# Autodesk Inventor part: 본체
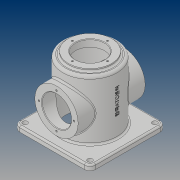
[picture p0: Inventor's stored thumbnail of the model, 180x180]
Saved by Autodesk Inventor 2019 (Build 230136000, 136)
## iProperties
Created: 2019-03
Part Number: 본체
Material: 일반
Document SubType Name: Modeling
Designer: PC312-08
Density: 1 g/cm^3
Appearance: 기본값
Mass: 414.937 g
Surface Area: 1160.06 cm^2
Volume: 414.937 cm^3
Author: PC312-08
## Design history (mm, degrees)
sketch "스케치1"
  geometry: C1 r 50 at (0, 0); 1 further point
  constraints: 1 centre point, 1 coincident
  dimensions: "d0" = 100 diameter of C1
extrude "돌출1" new body sketch "스케치1" stored distance "d1" = 110; taper "d2" = 0 deg
sketch "스케치2"
  geometry: L1 (-70, -70)-(70, -70); L2 (70, -70)-(70, 70); L3 (70, 70)-(-70, 70); L4 (-70, 70)-(-70, -70); L5 (-70, -70)-(70, 70); L6 (70, -70)-(-70, 70); 1 further point
  constraints: 12 end point, 2 midpoint, 2 parallel, 1 horizontal, 1 perpendicular
  dimensions: "d3" = 140 distance of L3.end L2.end; "d4" = 140 distance of L2.end L1.end
extrude "돌출2" join sketch "스케치2" distance "d5" = 10; taper "d6" = 0 deg
sketch "스케치3"
  geometry: C1 r 40 at (0, 0); 1 further point
  constraints: 1 centre point, 1 coincident
  dimensions: "d7" = 80 diameter of C1
extrude "돌출3" join sketch "스케치3" distance "d8" = 5; taper "d9" = 0 deg
sketch "스케치4"
  geometry: C1 r 45 at (0, 0); 1 further point
  constraints: 1 centre point, 1 coincident
  dimensions: "d10" = 90 diameter of C1
extrude "돌출4" cut sketch "스케치4" distance "d11" = 112; taper "d12" = 0 deg
sketch "스케치5"
  geometry: C1 r 27 at (0, 0); 1 further point
  constraints: 1 centre point, 1 coincident
  dimensions: "d13" = 54 diameter of C1
extrude "돌출5" cut sketch "스케치5" distance "d14" = 13; taper "d15" = 0 deg
node "작업 평면1"
sketch "스케치6"
  geometry: L1 (70, -65)-(-70, -65) reference; C1 r 40 at (0, -5); 1 further point
  constraints: 1 centre point, 1 vertical alignment
  dimensions: "d17" = 80 diameter of C1; "d18" = 60 distance from line of L1 C1.centre
extrude "돌출6" join sketch "스케치6" stored distance "d19" = 13; taper "d20" = 0 deg
sketch "스케치7" dims "d21" = 65
  geometry: L1 (70, -60)-(-70, -60) reference; L2 (0, 0)-(0, 32.5); 2 further points
  constraints: 2 end point, 2 vertical alignment, 1 coincident, 1 vertical, 2 other
  dimensions: "d22" = 60 distance from line of L1 L2.start
hole "구멍1" sketch "스케치7" at (0, 32.5) diameter "d23" = 3.242; stored, may be unused: countersink angle "d27" = 90 deg, drill point angle "d29" = 118 deg; dims "d24" = 8, "d25" = 4, "d26" = 2, "d28" = 10
sketch "스케치8"
  geometry: L1 (70, -60)-(-70, -60) reference; C1 r 27 at (0, 0); 1 further point
  constraints: 1 centre point, 1 vertical alignment
  dimensions: "d33" = 54 diameter of C1; "d34" = 60 distance from line of L1 C1.centre
extrude "돌출7" cut sketch "스케치8" stored distance "d35" = 13; taper "d36" = 0 deg
sketch "스케치10" dims "d37" = 65
  geometry: L1 (0, 0)-(0, 32.5); 2 further points
  constraints: 2 coincident, 2 end point, 1 vertical, 1 vertical alignment, 2 other
hole "구멍2" sketch "스케치10" at (0, 32.5) diameter "d38" = 3.242; stored, may be unused: countersink angle "d42" = 90 deg, drill point angle "d44" = 118 deg; dims "d39" = 8, "d40" = 4, "d41" = 2, "d43" = 10
fillet "모깎기1" dims "d48" = 10
sketch "스케치11"
  geometry: A1 r 10 centre (-60, -60) between (-70, -60) and (-60, -70) reference; A2 r 10 centre (-60, 60) between (-60, 70) and (-70, 60) reference; A3 r 10 centre (60, 60) between (70, 60) and (60, 70) reference; A4 r 10 centre (60, -60) between (60, -70) and (70, -60) reference; 5 further points
  constraints: 4 coincident
hole "구멍3" sketch "스케치11" at (-60, -60), (-60, 60), (60, 60), (60, -60) diameter "d49" = 9; stored, may be unused: countersink angle "d53" = 90 deg, drill point angle "d55" = 118 deg; dims "d50" = 8, "d51" = 4, "d52" = 2, "d54" = 10
chamfer "모따기1" distance "d56" = 1; stored, may be unused: second distance "d57" = 2, angle "d58" = 45 deg
fillet "모깎기2" dims "d59" = 5
fillet "모깎기3" dims "d60" = 3
fillet "모깎기4" dims "d61" = 3
node "작업 평면2"
sketch "스케치12"
  geometry: L1 (-65, -60)-(-65, 60) reference; 2 further points
  constraints: 1 horizontal alignment, 1 other
  dimensions: "d63" = 70 distance from line of L1 point (5, 0)
feature "엠보싱1" sketch "스케치12" dims "d64" = 0.5, "d65" = 0
node "솔리드1"
pattern_circular "원형 패턴1" dims angle "d31" = 360 deg
mirror "미러1"
pattern_circular "원형 패턴2" dims angle "d46" = 360 deg
other parameters: "d16" = 62, "d62" = 53.25
